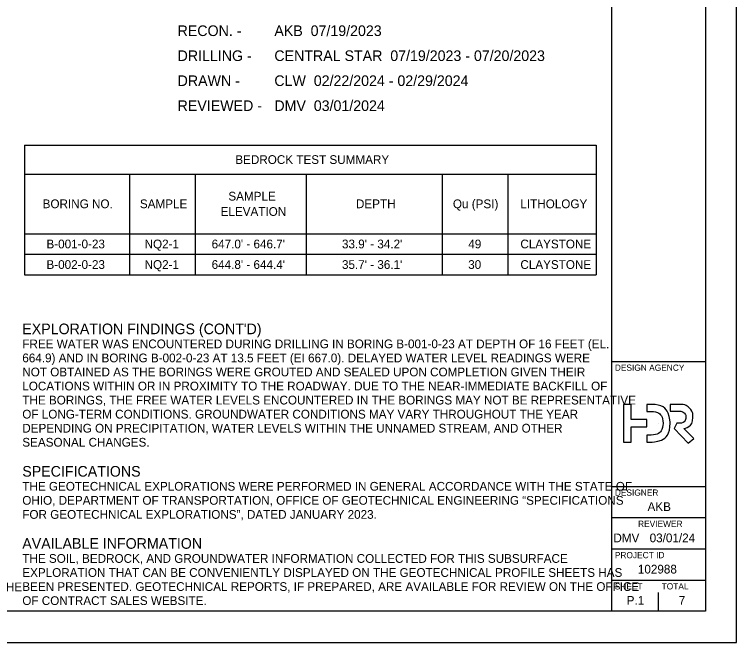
# Model space of a CAD drawing. Extents: x 0 to 34, y 0 to 22.
# Drawn here: x 22.43 to 34, y 0 to 10.05 of the extents above; entities that cross this region are included whole.
import ezdxf

# ---------------------------------------------------------------- set-up
doc = ezdxf.new("R2010")
doc.units = 0
for name, color, linetype in [('SH_Border', 7, 'Continuous'), ('SH_Cut_Line', 7, 'Continuous'), ('SH_Data', 7, 'Continuous'), ('SH_Text', 7, 'Continuous')]:
    doc.layers.add(name, color=color, linetype=linetype)

msp = doc.modelspace()

# ---------------------------------------------------------------- linework, layer by layer
at = {"layer": 'SH_Border'}
for p, q in [((32, 0.5), (32, 21.5)), ((32, 4.5), (33.5, 4.5)), ((32, 2.5), (33.5, 2.5)), ((32, 2), (33.5, 2)), ((32, 1.5), (33.5, 1.5)), ((32, 1), (33.5, 1))]:
    msp.add_line(p, q, dxfattribs=at)
msp.add_lwpolyline([(1.5, 21.5), (33.5, 21.5), (33.5, 0.5), (1.5, 0.5)], close=True, dxfattribs=at)
at = {"layer": 'SH_Cut_Line'}
msp.add_lwpolyline([(0, 0), (34, 0), (34, 22), (0, 22)], close=True, dxfattribs=at)
at = {"layer": 'SH_Data'}
for p, q in [((22.594, 7.961), (31.752, 7.961)), ((22.594, 7.961), (22.594, 5.886)), ((31.752, 7.961), (31.752, 5.886)), ((22.594, 7.5), (31.752, 7.5)), ((24.274, 7.5), (24.274, 5.886)), ((25.329, 7.5), (25.329, 5.886)), ((27.107, 7.5), (27.107, 5.886)), ((29.282, 7.5), (29.282, 5.886)), ((30.336, 7.5), (30.336, 5.886)), ((22.594, 6.545), (31.752, 6.545)), ((22.594, 6.215), (31.752, 6.215)), ((22.594, 5.886), (31.752, 5.886)), ((32.75, 3.5), (32.75, 3.5)), ((32.75, 0.5), (32.75, 0.8)), ((32.375, 0.675), (32.375, 0.675))]:
    msp.add_line(p, q, dxfattribs=at)
msp.add_lwpolyline([(32.565, 3.571), (32.311, 3.571), (32.311, 3.813), (32.189, 3.813), (32.189, 3.209), (32.311, 3.209), (32.311, 3.451), (32.565, 3.451)], close=True, dxfattribs=at)
for points in [[(32.634, 3.813), (32.562, 3.813), (32.562, 3.7), (32.634, 3.7)], [(33.063, 3.813), (32.935, 3.813), (32.935, 3.704), (33.072, 3.704)], [(32.936, 3.511), (32.936, 3.511), (32.936, 3.511), (32.936, 3.512), (32.936, 3.512)], [(33.077, 3.51), (33.043, 3.51), (33.003, 3.424), (33.226, 3.192), (33.313, 3.265), (33.155, 3.425)], [(32.634, 3.322), (32.562, 3.322), (32.562, 3.209), (32.634, 3.209)]]:
    msp.add_lwpolyline(points, dxfattribs=at)
for points in [[(32.936, 3.512), (32.936, 3.512), (32.935, 3.686), (32.808, 3.813), (32.634, 3.813)], [(33.239, 3.759), (33.239, 3.759), (33.193, 3.802), (33.141, 3.813), (33.063, 3.813)], [(33.072, 3.704), (33.072, 3.704), (33.113, 3.704), (33.141, 3.696), (33.161, 3.676)], [(33.302, 3.605), (33.302, 3.605), (33.302, 3.668), (33.284, 3.716), (33.239, 3.759)], [(32.634, 3.7), (32.634, 3.7), (32.744, 3.7), (32.822, 3.622), (32.822, 3.511)], [(33.189, 3.607), (33.189, 3.607), (33.189, 3.546), (33.136, 3.51), (33.077, 3.51)], [(33.155, 3.425), (33.155, 3.425), (33.242, 3.441), (33.302, 3.521), (33.302, 3.605)], [(33.161, 3.676), (33.161, 3.676), (33.179, 3.658), (33.189, 3.634), (33.189, 3.607)], [(32.822, 3.511), (32.822, 3.511), (32.822, 3.4), (32.744, 3.322), (32.634, 3.322)], [(32.634, 3.209), (32.634, 3.209), (32.808, 3.209), (32.935, 3.336), (32.936, 3.511)]]:
    msp.add_open_spline(points, degree=3, dxfattribs=at)

# ---------------------------------------------------------------- texts
for s, height, p in [('DESIGN AGENCY', 0.1, (32.05, 4.35)), ('DESIGNER', 0.1, (32.05, 2.35)), ('AKB', 0.14, (32.574, 2.105)), ('REVIEWER', 0.1, (32.422, 1.85)), ('DMV', 0.14, (32.027, 1.605)), ('03/01/24', 0.14, (32.608, 1.605)), ('PROJECT ID', 0.1, (32.05, 1.35)), ('102988', 0.14, (32.419, 1.105)), ('SHEET', 0.1, (32.05, 0.85)), ('TOTAL', 0.1, (32.8, 0.85)), ('P.1', 0.14, (32.24, 0.605)), ('7', 0.14, (33.074, 0.605))]:
    msp.add_text(s, height=height, dxfattribs=at).set_placement(p)
at = {"layer": 'SH_Text'}
for s, height, p in [('RECON. -', 0.17, (25.046, 9.709)), ('AKB  07/19/2023', 0.17, (26.596, 9.709)), ('CENTRAL STAR  07/19/2023 - 07/20/2023', 0.17, (26.596, 9.309)), ('DRILLING -', 0.17, (25.046, 9.309)), ('DRAWN -', 0.17, (25.046, 8.909)), ('CLW  02/22/2024 - 02/29/2024', 0.17, (26.596, 8.909)), ('REVIEWED -', 0.17, (25.046, 8.509)), ('DMV  03/01/2024', 0.17, (26.596, 8.509)), ('BEDROCK TEST SUMMARY', 0.14, (25.97, 7.661)), ('SAMPLE ', 0.14, (25.859, 7.075)), ('BORING NO.', 0.14, (22.884, 6.953)), ('SAMPLE', 0.14, (24.442, 6.953)), ('DEPTH', 0.14, (27.903, 6.953)), ('Qu (PSI)', 0.14, (29.456, 6.953)), ('LITHOLOGY', 0.14, (30.537, 6.953)), ('ELEVATION', 0.14, (25.735, 6.83)), ('B-001-0-23', 0.14, (22.945, 6.31)), ('NQ2-1', 0.14, (24.517, 6.31)), ("647.0' - 646.7'", 0.14, (25.591, 6.31)), ("33.9' - 34.2'", 0.14, (27.679, 6.31)), ('49', 0.14, (29.702, 6.31)), ('CLAYSTONE', 0.14, (30.537, 6.31)), ('B-002-0-23', 0.14, (22.945, 5.981)), ('NQ2-1', 0.14, (24.517, 5.981)), ("644.8' - 644.4'", 0.14, (25.591, 5.981)), ("35.7' - 36.1'", 0.14, (27.679, 5.981)), ('30', 0.14, (29.701, 5.981)), ('CLAYSTONE', 0.14, (30.537, 5.981)), ("EXPLORATION FINDINGS (CONT'D)", 0.17, (22.558, 4.936)), ('FREE WATER WAS ENCOUNTERED DURING DRILLING IN BORING B-001-0-23 AT DEPTH OF 16 FEET (EL. ', 0.14, (22.558, 4.711)), ('664.9) AND IN BORING B-002-0-23 AT 13.5 FEET (EI 667.0). DELAYED WATER LEVEL READINGS WERE ', 0.14, (22.558, 4.486)), ('NOT OBTAINED AS THE BORINGS WERE GROUTED AND SEALED UPON COMPLETION GIVEN THEIR ', 0.14, (22.558, 4.261)), ('LOCATIONS WITHIN OR IN PROXIMITY TO THE ROADWAY. DUE TO THE NEAR-IMMEDIATE BACKFILL OF ', 0.14, (22.558, 4.036)), ('THE BORINGS, THE FREE WATER LEVELS ENCOUNTERED IN THE BORINGS MAY NOT BE REPRESENTATIVE ', 0.14, (22.558, 3.811)), ('OF LONG-TERM CONDITIONS. GROUNDWATER CONDITIONS MAY VARY THROUGHOUT THE YEAR ', 0.14, (22.558, 3.586)), ('DEPENDING ON PRECIPITATION, WATER LEVELS WITHIN THE UNNAMED STREAM, AND OTHER ', 0.14, (22.558, 3.361)), ('SEASONAL CHANGES.', 0.14, (22.558, 3.136)), ('SPECIFICATIONS', 0.17, (22.558, 2.656)), ('THE GEOTECHNICAL EXPLORATIONS WERE PERFORMED IN GENERAL ACCORDANCE WITH THE STATE OF ', 0.14, (22.558, 2.431)), ('OHIO, DEPARTMENT OF TRANSPORTATION, OFFICE OF GEOTECHNICAL ENGINEERING “SPECIFICATIONS ', 0.14, (22.558, 2.206)), ('FOR GEOTECHNICAL EXPLORATIONS”, DATED JANUARY 2023.', 0.14, (22.558, 1.981)), ('AVAILABLE INFORMATION', 0.17, (22.558, 1.501)), ('THE SOIL, BEDROCK, AND GROUNDWATER INFORMATION COLLECTED FOR THIS SUBSURFACE ', 0.14, (22.558, 1.276)), ('EXPLORATION THAT CAN BE CONVENIENTLY DISPLAYED ON THE GEOTECHNICAL PROFILE SHEETS HAS ', 0.14, (22.558, 1.051)), ('CONSISTS OF MODERATELY TO SEVERELY WEATHERED, VERY WEAK, GRAY CLAYSTONE. RQD VALUES FOR THE ', 0.14, (12.122, 0.821)), ('BEEN PRESENTED. GEOTECHNICAL REPORTS, IF PREPARED, ARE AVAILABLE FOR REVIEW ON THE OFFICE ', 0.14, (22.558, 0.826)), ('OF CONTRACT SALES WEBSITE.', 0.14, (22.558, 0.601))]:
    msp.add_text(s, height=height, dxfattribs=at).set_placement(p)

doc.saveas('drawing.dxf')
